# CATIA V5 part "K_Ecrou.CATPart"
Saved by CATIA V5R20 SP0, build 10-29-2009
Part number: Ecrou
Bounding box of the stored display mesh (mm): x -201 to -161, y -289.606 to 5, z -60 to 60
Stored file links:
  G:\Khaled_CFAO_2011\ST2M\ST2M_GR2\jcoetard\Khaled\CAD_CATIA\K_Ecrou.CATPart
  J:\Thinkmotion\Thinkmotion_COETARD\Maquette_catia\Maquette_catia_R20_Licence_education\jcharlescoetard.CATPRODUCT\Assemblage_Pince_Prehension_Mors_Paralleles.CATProduct
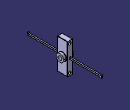
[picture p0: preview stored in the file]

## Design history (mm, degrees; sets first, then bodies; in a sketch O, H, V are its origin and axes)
Set1
  Plane1 "Plan_écrou": linked copy from another document
  Point1: linked copy from another document
  Point2 "Point.12": linked copy from another document
  Point3 "Point_centre_écrou": linked copy from another document
  Line1 "Axe_pivot_écrou_1": linked copy from another document
  Line2 "Axe_pivot_écrou_2": linked copy from another document
Body1 (main body)
  Sketch1 on Plane1, origin (-171, 0, 0), H (0, 1, 0), V (0, 0, 1)
    line L1 (-162.3026, 60) -> (-122.3026, 60)
    line L2 (-122.3026, 60) -> (-122.3026, -60)
    line L3 (-122.3026, -60) -> (-162.3026, -60)
    line L4 (-162.3026, -60) -> (-162.3026, 60)
    reference projected line E1 through (0, 50) direction (1, 0) from Line1
    reference projected line E2 through (0, -50) direction (1, 0) from Line2
    reference projected point E3 (-142.303, 0) from Point3
    reference projected point E4 (-142.303, 0) from Point3
    distance L1 E1 = 10
    distance L3 E2 = 10
    distance L4 E3 = 19.9996
    distance L2 E4 = 20.0004
    horizontal: L1 H, L3 H
    vertical: L2 V, L4 V
  Pad1: profile Sketch1, direction (-1, 0, 0), length 20
  Sketch2 on start face of Pad1, origin (-171, 0, 0), H (0, 1, 0), V (0, 0, 1)
    circle A1 centre (-142.303, 0) radius 15
    point P1 (-142.303, 0)
    construction line L1 (-141.3197, 0) -> (-26.5096, 0)
    point P2 (-141.3197, 0)
    axis line L2 (-142.303, 41.9223) -> (-142.303, -67.4615)
    reference projected point E1 (-142.303, 0) from Point3
    distance L2 = 20
    coincidence: P2 H, P1 L1, P1 L2
    horizontal: L1 H
    vertical: L2 V
    concentricity: A1 E1
  Pad2: profile Sketch2, direction (1, 0, 0), length 10
  Sketch3 on end face of Pad1, origin (-191, 0, 0), H (0, -1, 0), V (0, 0, 1)
    circle A1 centre (142.3026, 0) radius 15
    point P1 (142.3026, 0)
    construction line L1 (142.3026, 36.3189) -> (142.3026, -42.4289)
    reference projected line E1 (162.3026, 26.6667) -> (162.3026, -26.6667) from edge [end face of Pad1 | face of Pad1 from Sketch1.L4]
    axis line L2 (41.5438, 0) -> (165.9171, 0)
    point P4 (41.5438, 0)
    distance L1 E1 = 20
    vertical: L1 V
    coincidence: P4 H, L2 P1, P1 L1
    horizontal: L2 H
  Pad3: profile Sketch3, direction (-1, 0, 0), length 10
  Sketch4 on face of Pad1 from Sketch1.L2, origin (0, -122.3026, 0), H (-1, 0, 0), V (0, 0, 1)
    line L1 (178, 3) -> (184, 3)
    line L2 (184, 3) -> (184, -3)
    line L3 (184, -3) -> (178, -3)
    line L4 (178, -3) -> (178, 3)
    reference projected line E1 (191, -26.6667) -> (191, 26.6667) from edge [end face of Pad1 | face of Pad1 from Sketch1.L2]
    reference projected line E2 (171, -26.6667) -> (171, 26.6667) from edge [face of Pad1 from Sketch1.L2 | start face of Pad1]
    axis line L5 (4.2267, 0) -> (58.7074, 0)
    point P5 (4.2267, 0)
    distance L2 E1 = 7
    distance L4 E2 = 7
    length L2 = 6
    distance L3 L5 = 3
    horizontal: L1 H, L3 H, L5 H
    vertical: L2 V, L4 V
    coincidence: P5 H
  Pad4: profile Sketch4, direction (0, 1, 0), length 122.303
  Sketch5 on end face of Pad4, origin (0, 0.0004, 0), H (-1, 0, 0), V (0, 0, 1)
    line L1 (178, 5) -> (184, 5)
    line L2 (184, 5) -> (184, -5)
    line L3 (184, -5) -> (178, -5)
    line L4 (178, -5) -> (178, 5)
    reference projected line E1 (184, -3) -> (184, 3) from edge [face of Pad4 from Sketch4.L2 | end face of Pad4]
    reference projected line E2 (178, 3) -> (178, -3) from edge [face of Pad4 from Sketch4.L4 | end face of Pad4]
    reference projected line E3 (17, -3) -> (23, -3) from edge [face of Pad4 from Sketch4.L3 | end face of Pad4]
    reference projected line E4 (23, 3) -> (17, 3) from edge [face of Pad4 from Sketch4.L1 | end face of Pad4]
    distance L3 E3 = 2
    distance L1 E4 = 2
    horizontal: L1 H, L3 H
    vertical: L2 V, L4 V
    coincidence: L2 E1, L4 E2
  Pad5: profile Sketch5, direction (0, 1, 0), length 5
  Sketch6 on face of Pad1 from Sketch1.L2, origin (-60, -122.3026, 33.3333), H (1, 0, 0), V (0, 0, -1)
    point P1 (-120, -16.6667)
    reference projected point E1 (-120, -16.6667) from Point1
    coincidence: E1 P1
  Hole1: placed by Sketch6, at (-180, -122.3026, 50) direction (0, -1, 0), diameter 10, depth 100
  Sketch7 on face of Pad1 from Sketch1.L2, origin (-60, -122.3026, -33.3333), H (1, 0, 0), V (0, 0, -1)
    point P1 (-120, 16.6667)
    reference projected point E1 (-120, 16.6667) from Point2
    coincidence: E1 P1
  Hole2: placed by Sketch7, at (-180, -122.3026, -50) direction (0, -1, 0), diameter 10, depth 100
  Sketch8 on end face of Pad2, origin (-161, -86.303, 0), H (0, 1, 0), V (0, 0, 1)
    point P1 (-56, 0)
    reference projected point E1 (-56, 0) from Point3
    coincidence: E1 P1
  Hole3: placed by Sketch8, at (-161, -142.303, 0) direction (-1, 0, 0), diameter 15, depth 100
  Sketch9 on face of Pad1 from Sketch1.L4, origin (0, -162.3026, 0), H (1, 0, 0), V (0, 0, 1)
    line L1 (-184, 3) -> (-178, 3)
    line L2 (-178, 3) -> (-178, -3)
    line L3 (-178, -3) -> (-184, -3)
    line L4 (-184, -3) -> (-184, 3)
    reference projected line E1 (-171, 56.6667) -> (-171, -56.6667) from edge [face of Pad1 from Sketch1.L4 | start face of Pad1]
    reference projected line E2 (-191, 56.6667) -> (-191, -56.6667) from edge [end face of Pad1 | face of Pad1 from Sketch1.L4]
    distance L2 E1 = 7
    distance L4 E2 = 7
    length L2 = 6
    horizontal: L1 H, L3 H
    vertical: L2 V, L4 V
  Pad6: profile Sketch9, direction (0, -1, 0), length 122.303
  Sketch10 on end face of Pad6, origin (0, -284.6056, 0), H (1, 0, 0), V (0, 0, 1)
    line L1 (-184, 5) -> (-178, 5)
    line L2 (-178, 5) -> (-178, -5)
    line L3 (-178, -5) -> (-184, -5)
    line L4 (-184, -5) -> (-184, 5)
    reference projected line E1 (-178, -3) -> (-178, 3) from edge [face of Pad6 from Sketch9.L2 | end face of Pad6]
    reference projected line E2 (-184, 3) -> (-184, -3) from edge [face of Pad6 from Sketch9.L4 | end face of Pad6]
    axis line L5 (-212, 0) -> (-143, 0)
    point P5 (-212, 0)
    distance L1 L5 = 5
    length L2 = 10
    horizontal: L1 H, L3 H, L5 H
    vertical: L2 V, L4 V
    coincidence: L2 E1, L4 E2, P5 H
  Pad7: profile Sketch10, direction (0, -1, 0), length 5
  Fillet1: radius 0.5, on face of Pad6 from Sketch9.L3; face of Pad7 (x2); end face of Pad7; face of Pad6 from Sketch9.L1
  Fillet2: radius 0.5, on end face of Pad5; face of Pad4 from Sketch4.L3; face of Pad5; face of Pad4 from Sketch4.L1; edge [face of Pad5 | face of Pad4 from Sketch4.L3]
  Fillet3: radius 1, on end face of Pad1; start face of Pad1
